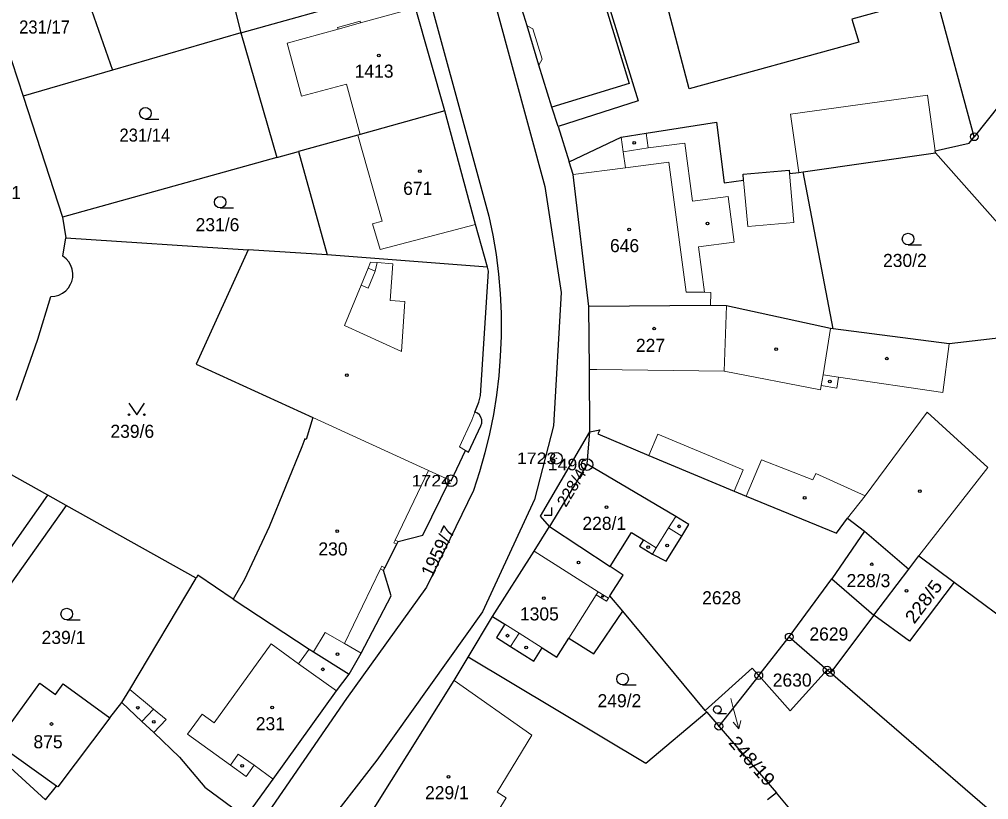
# Model space of a CAD drawing. Extents: x -679733 to -673243, y -1075091 to -1066557.
# Drawn here: x -676181.6 to -676055.6, y -1071788.5 to -1071687 of the extents above; entities that cross this region are included whole.
import ezdxf
from ezdxf.enums import TextEntityAlignment as Align

# ---------------------------------------------------------------- set-up
doc = ezdxf.new("R2010")
doc.units = 0
doc.header["$LTSCALE"] = 0.68
for name, color, linetype, lineweight in [('1', 7, 'Continuous', 25), ('3', 7, 'Continuous', 25), ('4', 7, 'Continuous', 13), ('5', 7, 'Continuous', 25), ('7', 7, 'Continuous', 13), ('8', 7, 'Continuous', 25)]:
    doc.layers.add(name, color=color, linetype=linetype, lineweight=lineweight)
doc.layers.add('2', color=7, linetype='Continuous')

msp = doc.modelspace()

# ---------------------------------------------------------------- linework, layer by layer
at = {"layer": '1'}
for p, q in [((-676057.44, -1071702.25), (-676066.33, -1071669.3)), ((-676152.82, -1071688.75), (-676130.95, -1071682.6)), ((-676181.15, -1071696.97), (-676176.04, -1071712.7)), ((-676111.57, -1071700.93), (-676112.37, -1071698.39)), ((-676111.57, -1071700.93), (-676110.14, -1071705.5)), ((-676062.48, -1071704.34), (-676042.38, -1071727.03)), ((-676075.79, -1071727.22), (-676079.69, -1071706.8)), ((-676107.78, -1071744.81), (-676107.45, -1071740.64)), ((-676175.55, -1071750.2), (-676177.92, -1071748.87)), ((-676071.71, -1071753.55), (-676065.95, -1071758.47)), ((-676092.44, -1071776.86), (-676103.16, -1071763.95)), ((-676070.48, -1071764.46), (-676076.15, -1071771.95)), ((-676081.51, -1071767.29), (-676076.59, -1071771.59)), ((-676169.85, -1071777.83), (-676168.29, -1071775.82))]:
    msp.add_line(p, q, dxfattribs=at)
for points in [[(-676099.38, -1071590.43), (-676125.1, -1071603.36), (-676134.03, -1071611.63), (-676132.28, -1071638.9), (-676113.31, -1071708.7), (-676111.17, -1071722.51), (-676112.16, -1071739.84), (-676114.63, -1071749.43), (-676121.41, -1071764.03), (-676135.15, -1071783.33), (-676142.46, -1071792.76), (-676166.36, -1071822.04), (-676175.39, -1071833.12), (-676182.45, -1071844.4), (-676187.2, -1071855.01), (-676191.45, -1071871.27), (-676192.51, -1071884.43), (-676191.2, -1071899.37), (-676183.88, -1071917.06), (-676171.89, -1071936.65), (-676157.14, -1071950.29), (-676143.77, -1071959.8), (-676108.24, -1071982.64), (-676103.47, -1071979.82)], [(-676152.11, -1071615.93), (-676148.36, -1071616.28), (-676140.37, -1071639.9), (-676120.56, -1071712.56)], [(-676103.2, -1071654.04), (-676086.03, -1071649.36), (-676082.9, -1071651.16), (-676076.65, -1071673.87), (-676071.5, -1071672.48), (-676068, -1071685.48), (-676073.36, -1071686.93), (-676072.45, -1071689.95), (-676094.51, -1071696.03), (-676097.54, -1071684.49)], [(-676112.37, -1071698.39), (-676114.06, -1071692.92), (-676115.61, -1071687.82), (-676116.03, -1071686.43), (-676117.44, -1071681.82), (-676117.87, -1071680.43), (-676119.29, -1071675.81), (-676119.65, -1071674.63), (-676121.9, -1071667.28), (-676122.44, -1071665.53), (-676123.73, -1071661.42)], [(-676042.96, -1071662.97), (-676040.87, -1071672.83), (-676039.2, -1071679.27), (-676057.44, -1071702.25)], [(-676111.15, -1071665.03), (-676104.63, -1071686.35), (-676101.17, -1071697.56), (-676111.57, -1071700.93)], [(-676119.65, -1071674.63), (-676117.65, -1071670.88), (-676116.48, -1071670.53), (-676115.77, -1071670.87), (-676112.25, -1071669.86), (-676111.85, -1071669.11), (-676110.46, -1071668.68), (-676102.32, -1071695.32), (-676112.37, -1071698.39)], [(-676148.81, -1071669.62), (-676151.07, -1071670.28), (-676157.09, -1071671.95), (-676152.82, -1071688.75), (-676148.14, -1071704.96), (-676145.33, -1071704.18)], [(-676174.48, -1071676.86), (-676175.28, -1071677.08), (-676169.53, -1071693.6)], [(-676186.72, -1071680.18), (-676184.08, -1071687.93), (-676181.15, -1071696.97)], [(-676126.28, -1071698.88), (-676130.13, -1071685.49), (-676130.95, -1071682.6)], [(-676152.82, -1071688.75), (-676169.53, -1071693.6), (-676181.15, -1071696.97)], [(-676126.28, -1071698.88), (-676137.33, -1071701.97), (-676137.62, -1071702.05), (-676145.33, -1071704.18), (-676141.6, -1071717.61)], [(-676120.74, -1071719.2), (-676122.3, -1071713.65), (-676126.28, -1071698.88)], [(-676110.14, -1071705.5), (-676103.36, -1071702.29), (-676100.12, -1071701.77), (-676090.96, -1071700.35), (-676089.95, -1071708.22), (-676087.44, -1071707.87), (-676087.51, -1071707.12), (-676081.5, -1071706.6), (-676081.46, -1071707.04), (-676080.26, -1071706.88), (-676079.69, -1071706.8), (-676062.48, -1071704.34)], [(-676062.48, -1071704.34), (-676062.52, -1071704.09), (-676058.1, -1071703.08), (-676057.44, -1071702.25)], [(-676148.14, -1071704.96), (-676176.04, -1071712.7), (-676175.61, -1071715.39), (-676151.9, -1071716.94)], [(-676107.55, -1071724.3), (-676109.62, -1071707.17), (-676110.14, -1071705.5)], [(-676120.56, -1071712.56), (-676120.048, -1071715.059), (-676119.634, -1071717.577), (-676119.319, -1071720.109), (-676119.103, -1071722.651), (-676118.987, -1071725.2), (-676118.971, -1071727.751), (-676118.98, -1071728.231), (-676119.083, -1071730.78), (-676119.285, -1071733.323), (-676119.588, -1071735.857), (-676119.989, -1071738.376), (-676120.489, -1071740.878), (-676121.086, -1071743.359), (-676121.78, -1071745.814), (-676122.57, -1071748.24)], [(-676177.55, -1071723.03), (-676177.018, -1071722.983), (-676176.504, -1071722.837), (-676176.026, -1071722.598), (-676175.601, -1071722.275), (-676175.243, -1071721.878), (-676174.966, -1071721.421), (-676174.822, -1071721.065), (-676174.704, -1071720.544), (-676174.685, -1071720.01), (-676174.765, -1071719.482), (-676174.943, -1071718.978), (-676175.211, -1071718.516), (-676175.561, -1071718.112), (-676175.98, -1071717.78), (-676175.61, -1071715.39)], [(-676151.9, -1071716.94), (-676158.66, -1071731.81), (-676143.45, -1071738.76), (-676144.34, -1071741.61), (-676144.49, -1071741.53), (-676144.89, -1071742.57), (-676149.15, -1071752.96), (-676152.35, -1071759.83), (-676153.84, -1071762.37)], [(-676120.74, -1071719.2), (-676141.6, -1071717.61), (-676151.9, -1071716.94)], [(-676122.39, -1071738.06), (-676121.89, -1071736.77), (-676121.68, -1071735.9), (-676120.6, -1071719.71), (-676120.74, -1071719.2)], [(-676182.03, -1071736.5), (-676179.22, -1071728.58), (-676177.55, -1071723.03)], [(-676075.79, -1071727.22), (-676076.13, -1071727.18), (-676089.68, -1071724.22), (-676091.73, -1071724.19), (-676107.55, -1071724.3)], [(-676107.45, -1071740.64), (-676107.5, -1071732.52), (-676107.55, -1071724.3)], [(-676042.38, -1071727.03), (-676060.72, -1071729.17), (-676075.79, -1071727.22)], [(-676121.62, -1071739.82), (-676121.506, -1071739.486), (-676121.491, -1071739.134), (-676121.5, -1071739.061), (-676121.604, -1071738.724), (-676121.799, -1071738.43), (-676122.068, -1071738.203), (-676122.39, -1071738.06)], [(-676138.75, -1071772.14), (-676137.2, -1071769.4), (-676133.27, -1071761.96), (-676134.28, -1071758.66), (-676134.1, -1071758.3), (-676132.55, -1071755.25), (-676132.37, -1071754.9), (-676129.16, -1071754.05), (-676125.64, -1071746.89), (-676125.49, -1071746.98), (-676123.61, -1071743.03), (-676123.24, -1071743.26), (-676121.62, -1071739.82)], [(-676112.69, -1071752.95), (-676113.86, -1071751.58), (-676107.45, -1071740.64)], [(-676107.45, -1071740.64), (-676106.12, -1071740.38), (-676106.39, -1071740.9), (-676099.76, -1071743.68), (-676088.67, -1071748.33), (-676087.1, -1071748.99), (-676075.34, -1071753.78), (-676073.91, -1071751.86), (-676071.71, -1071753.55)], [(-676195.04, -1071773.17), (-676177.92, -1071748.87), (-676185.65, -1071744.56)], [(-676107.78, -1071744.81), (-676112.69, -1071752.95), (-676104.8, -1071758.15)], [(-676104.8, -1071758.15), (-676102.03, -1071753.7), (-676100.48, -1071754.66), (-676100.99, -1071755.47), (-676099.3, -1071756.52), (-676097.52, -1071757.44), (-676095.49, -1071754.18), (-676094.57, -1071752.69), (-676096.27, -1071751.63), (-676107.78, -1071744.81)], [(-676122.57, -1071748.24), (-676128.67, -1071760.82), (-676139.08, -1071775.3), (-676150.18, -1071791.44), (-676172.35, -1071816.74), (-676187.37, -1071835.51)], [(-676168.29, -1071775.82), (-676167.29, -1071774.14), (-676158.64, -1071759.64), (-676175.55, -1071750.2), (-676193.13, -1071774.91), (-676178.23, -1071788.5), (-676176.79, -1071786.69)], [(-676120.09, -1071764.63), (-676114.68, -1071756.12), (-676112.69, -1071752.95)], [(-676071.71, -1071753.55), (-676075.98, -1071759.72), (-676070.48, -1071764.46), (-676065.95, -1071758.47)], [(-676065.95, -1071758.47), (-676064.66, -1071756.76), (-676060.06, -1071760.17)], [(-676103.16, -1071763.95), (-676104.82, -1071761.95), (-676103.11, -1071759.26), (-676104.8, -1071758.15)], [(-676153.84, -1071762.37), (-676158.41, -1071759.25), (-676158.64, -1071759.64)], [(-676085.46, -1071772.32), (-676081.51, -1071767.29), (-676075.98, -1071759.72)], [(-676060.06, -1071760.17), (-676065.84, -1071767.86), (-676070.48, -1071764.46)], [(-676060.06, -1071760.17), (-676050.81, -1071767.02), (-676048.46, -1071763.85)], [(-676153.84, -1071762.37), (-676143.93, -1071768.88), (-676143.36, -1071769.24), (-676138.75, -1071772.14)], [(-676137.29, -1071792.46), (-676125.09, -1071772.94), (-676123.26, -1071769.92), (-676120.09, -1071764.63)], [(-676120.09, -1071764.63), (-676118.51, -1071765.64), (-676119.59, -1071767.35), (-676117.74, -1071768.53), (-676114.72, -1071770.44), (-676113.63, -1071768.73), (-676111.75, -1071769.93), (-676110.17, -1071767.45), (-676106.92, -1071769.51), (-676103.16, -1071763.95)], [(-676092.24, -1071777.09), (-676100.15, -1071783.77), (-676123.26, -1071769.92)], [(-676152.21, -1071790.73), (-676151.78, -1071790.15), (-676148.63, -1071785.79), (-676140.41, -1071774.31), (-676138.75, -1071772.14)], [(-676085.46, -1071772.32), (-676086.32, -1071771.35), (-676092.44, -1071776.86)], [(-676085.46, -1071772.32), (-676090.66, -1071778.91), (-676083.15, -1071787.56)], [(-676076.59, -1071771.59), (-676081.39, -1071776.9), (-676085.46, -1071772.32)], [(-676044.62, -1071799.18), (-676076.15, -1071771.95), (-676076.59, -1071771.59)], [(-676176.79, -1071786.69), (-676184.64, -1071781.1), (-676178.96, -1071773.29), (-676176.94, -1071774.76), (-676175.94, -1071773.39), (-676169.85, -1071777.83)], [(-676168.29, -1071775.82), (-676165.7, -1071778.29), (-676164.16, -1071779.74), (-676160.82, -1071782.91), (-676157.5, -1071786.82), (-676152.21, -1071790.73)], [(-676092.44, -1071776.86), (-676092.24, -1071777.09), (-676090.66, -1071778.91)], [(-676169.85, -1071777.83), (-676176.63, -1071786.8), (-676176.79, -1071786.69)], [(-676067.25, -1071806.74), (-676075.34, -1071796.95), (-676083.15, -1071787.56), (-676084.33, -1071788.48)]]:
    msp.add_lwpolyline(points, dxfattribs=at)
at = {"layer": '3'}
for p, q in [((-676165.243, -1071699.94), (-676163.493, -1071699.94)), ((-676155.523, -1071711.5), (-676153.773, -1071711.5)), ((-676066.053, -1071716.3), (-676064.303, -1071716.3)), ((-676175.483, -1071765.07), (-676173.733, -1071765.07)), ((-676103.173, -1071773.52), (-676101.423, -1071773.52)), ((-676090.845, -1071777.24), (-676089.673, -1071777.24))]:
    msp.add_line(p, q, dxfattribs=at)
for points in [[(-676167.38, -1071736.889), (-676166.38, -1071738.39), (-676165.38, -1071736.889)], [(-676113.371, -1071751.45), (-676112.37, -1071751.45), (-676112.37, -1071750.45)]]:
    msp.add_lwpolyline(points, dxfattribs=at)
for centre, radius in [((-676165.2429, -1071699.1898), 0.75), ((-676155.5229, -1071710.7498), 0.75), ((-676066.0529, -1071715.5498), 0.75), ((-676167.38, -1071738.3895), 0.1), ((-676165.38, -1071738.3895), 0.1), ((-676175.4829, -1071764.3198), 0.75), ((-676103.1729, -1071772.7698), 0.75), ((-676090.8452, -1071776.7374), 0.5025)]:
    msp.add_circle(centre, radius, dxfattribs=at)
at = {"layer": '4'}
for p, q in [((-676137.25, -1071687.44), (-676130.13, -1071685.49)), ((-676140.24, -1071688.04), (-676137.31, -1071687.23)), ((-676140.18, -1071688.25), (-676137.25, -1071687.44)), ((-676137.31, -1071687.23), (-676137.25, -1071687.44)), ((-676115.61, -1071687.82), (-676114.86, -1071688.22)), ((-676146.79, -1071690.08), (-676140.18, -1071688.25)), ((-676140.18, -1071688.25), (-676140.24, -1071688.04)), ((-676114.86, -1071688.22), (-676113.65, -1071692.17)), ((-676144.95, -1071696.98), (-676146.79, -1071690.08)), ((-676113.65, -1071692.17), (-676114.06, -1071692.92)), ((-676139.08, -1071695.41), (-676144.95, -1071696.98)), ((-676137.33, -1071701.97), (-676139.08, -1071695.41)), ((-676081.34, -1071699.31), (-676063.53, -1071696.83)), ((-676063.53, -1071696.83), (-676062.52, -1071704.09)), ((-676081.34, -1071699.31), (-676080.26, -1071706.88)), ((-676099.87, -1071703.69), (-676100.12, -1071701.77)), ((-676134.47, -1071713.22), (-676137.62, -1071702.05)), ((-676103.09, -1071704.19), (-676103.36, -1071702.29)), ((-676099.87, -1071703.69), (-676095.08, -1071703.07)), ((-676095.08, -1071703.07), (-676094.09, -1071710.63)), ((-676102.78, -1071706.29), (-676097.15, -1071705.56)), ((-676097.15, -1071705.56), (-676094.92, -1071722.44)), ((-676109.62, -1071707.17), (-676102.78, -1071706.29)), ((-676086.9, -1071713.93), (-676087.44, -1071707.87)), ((-676081.46, -1071707.04), (-676080.89, -1071713.39)), ((-676094.09, -1071710.63), (-676089.44, -1071710.02)), ((-676089.44, -1071710.02), (-676088.66, -1071715.97)), ((-676135.72, -1071713.58), (-676134.47, -1071713.22)), ((-676134.71, -1071716.89), (-676135.72, -1071713.58)), ((-676122.3, -1071713.65), (-676134.71, -1071716.89)), ((-676080.89, -1071713.39), (-676086.9, -1071713.93)), ((-676088.66, -1071715.97), (-676093.29, -1071716.58)), ((-676093.29, -1071716.58), (-676092.51, -1071722.47)), ((-676136.29, -1071719.33), (-676137.2, -1071721.55)), ((-676135.96, -1071718.54), (-676136.29, -1071719.33)), ((-676135.12, -1071718.61), (-676135.96, -1071718.54)), ((-676133.07, -1071718.76), (-676135.12, -1071718.61)), ((-676133.07, -1071718.76), (-676133.39, -1071723.55)), ((-676135.36, -1071719.71), (-676136.28, -1071721.93)), ((-676137.2, -1071721.55), (-676139.36, -1071726.77)), ((-676136.28, -1071721.93), (-676137.2, -1071721.55)), ((-676094.92, -1071722.44), (-676092.51, -1071722.47)), ((-676092.51, -1071722.47), (-676091.71, -1071722.48)), ((-676091.71, -1071722.48), (-676091.73, -1071724.19)), ((-676133.39, -1071723.55), (-676131.5, -1071723.68)), ((-676131.93, -1071730.16), (-676131.5, -1071723.68)), ((-676089.68, -1071724.22), (-676089.95, -1071732.72)), ((-676131.93, -1071730.16), (-676139.36, -1071726.77)), ((-676077.1, -1071733.19), (-676076.13, -1071727.18)), ((-676061.52, -1071735.51), (-676060.72, -1071729.17)), ((-676107.5, -1071732.52), (-676106.51, -1071732.53)), ((-676106.51, -1071732.53), (-676089.95, -1071732.72)), ((-676089.95, -1071732.72), (-676077.42, -1071735.17)), ((-676077.33, -1071734.59), (-676077.1, -1071733.19)), ((-676077.1, -1071733.19), (-676075.08, -1071733.49)), ((-676077.42, -1071735.17), (-676077.33, -1071734.59)), ((-676077.33, -1071734.59), (-676075.31, -1071734.92)), ((-676075.31, -1071734.92), (-676075.08, -1071733.49)), ((-676075.08, -1071733.49), (-676061.52, -1071735.51)), ((-676122.8, -1071739.1), (-676122.39, -1071738.06)), ((-676071.64, -1071748.94), (-676063.57, -1071738.05)), ((-676063.57, -1071738.05), (-676055.69, -1071745.25)), ((-676143.45, -1071738.76), (-676128.42, -1071745.64)), ((-676124.39, -1071742.56), (-676122.8, -1071739.1)), ((-676099.76, -1071743.68), (-676098.6, -1071740.91)), ((-676098.6, -1071740.91), (-676087.51, -1071745.56)), ((-676123.61, -1071743.03), (-676124.39, -1071742.56)), ((-676085.12, -1071744.28), (-676087.1, -1071748.99)), ((-676085.12, -1071744.28), (-676078.42, -1071746.88)), ((-676128.42, -1071745.64), (-676132.77, -1071754.69)), ((-676128.42, -1071745.64), (-676125.64, -1071746.89)), ((-676087.51, -1071745.56), (-676088.67, -1071748.33)), ((-676055.69, -1071745.25), (-676064.66, -1071756.76)), ((-676078.42, -1071746.88), (-676078.05, -1071746.04)), ((-676078.05, -1071746.04), (-676071.64, -1071748.94)), ((-676073.91, -1071751.86), (-676071.64, -1071748.94)), ((-676097.19, -1071753.12), (-676096.27, -1071751.63)), ((-676098.8, -1071755.7), (-676097.19, -1071753.12)), ((-676097.19, -1071753.12), (-676095.49, -1071754.18)), ((-676132.95, -1071755.05), (-676132.77, -1071754.69)), ((-676132.77, -1071754.69), (-676132.37, -1071754.9)), ((-676100.48, -1071754.66), (-676098.8, -1071755.7)), ((-676132.55, -1071755.25), (-676132.95, -1071755.05)), ((-676099.3, -1071756.52), (-676098.8, -1071755.7)), ((-676114.68, -1071756.12), (-676106.34, -1071761.41)), ((-676139.35, -1071768.16), (-676134.68, -1071758.45)), ((-676134.68, -1071758.45), (-676134.5, -1071758.09)), ((-676134.28, -1071758.66), (-676134.68, -1071758.45)), ((-676134.5, -1071758.09), (-676134.1, -1071758.3)), ((-676106.6, -1071761.82), (-676110.17, -1071767.45)), ((-676106.34, -1071761.41), (-676106.6, -1071761.82)), ((-676105.28, -1071762.66), (-676106.6, -1071761.82)), ((-676105.02, -1071762.25), (-676106.34, -1071761.41)), ((-676105.02, -1071762.25), (-676105.28, -1071762.66)), ((-676104.82, -1071761.95), (-676105.02, -1071762.25)), ((-676118.51, -1071765.64), (-676116.65, -1071766.81)), ((-676143.36, -1071769.24), (-676141.85, -1071766.72)), ((-676141.85, -1071766.72), (-676139.35, -1071768.16)), ((-676116.65, -1071766.81), (-676117.74, -1071768.53)), ((-676116.65, -1071766.81), (-676113.63, -1071768.73)), ((-676156.29, -1071778.47), (-676148.89, -1071768.2)), ((-676148.89, -1071768.2), (-676145.32, -1071770.78)), ((-676139.35, -1071768.16), (-676137.2, -1071769.4)), ((-676145.32, -1071770.78), (-676143.93, -1071768.88)), ((-676145.32, -1071770.78), (-676140.41, -1071774.31)), ((-676125.09, -1071772.94), (-676114.97, -1071780.06)), ((-676167.29, -1071774.14), (-676164.19, -1071776.7)), ((-676164.19, -1071776.7), (-676165.7, -1071778.29)), ((-676164.19, -1071776.7), (-676162.55, -1071778.05)), ((-676159.77, -1071779.95), (-676157.88, -1071777.33)), ((-676157.88, -1071777.33), (-676156.29, -1071778.47)), ((-676162.55, -1071778.05), (-676164.16, -1071779.74)), ((-676154.19, -1071783.97), (-676159.77, -1071779.95)), ((-676114.97, -1071780.06), (-676119.48, -1071787.5)), ((-676154.19, -1071783.97), (-676153.16, -1071782.53)), ((-676153.16, -1071782.53), (-676151.12, -1071783.99)), ((-676152.16, -1071785.44), (-676154.19, -1071783.97)), ((-676151.12, -1071783.99), (-676152.16, -1071785.44)), ((-676148.63, -1071785.79), (-676151.12, -1071783.99)), ((-676119.48, -1071787.5), (-676118.32, -1071788.2)), ((-676118.32, -1071788.2), (-676121.02, -1071792.64))]:
    msp.add_line(p, q, dxfattribs=at)
for points in [[(-676102.78, -1071706.29), (-676103.09, -1071704.19), (-676099.87, -1071703.69)], [(-676135.12, -1071718.61), (-676135.36, -1071719.71), (-676136.29, -1071719.33)]]:
    msp.add_lwpolyline(points, dxfattribs=at)
at = {"layer": '5'}
for centre, radius in [((-676134.8968, -1071691.6792), 0.175), ((-676101.6568, -1071703.0292), 0.175), ((-676129.5568, -1071706.7192), 0.175), ((-676102.3268, -1071714.3092), 0.175), ((-676092.1468, -1071713.5192), 0.175), ((-676099.0768, -1071727.1992), 0.175), ((-676083.2168, -1071729.8592), 0.175), ((-676068.7968, -1071731.0992), 0.175), ((-676139.0568, -1071733.2392), 0.175), ((-676076.2268, -1071734.0592), 0.175), ((-676064.5268, -1071748.3492), 0.175), ((-676079.4968, -1071749.1892), 0.175), ((-676105.2768, -1071750.4192), 0.175), ((-676140.2868, -1071753.5292), 0.175), ((-676095.8368, -1071752.9092), 0.175), ((-676099.8468, -1071755.6292), 0.175), ((-676097.3768, -1071755.3892), 0.175), ((-676108.8968, -1071757.5992), 0.175), ((-676070.7768, -1071757.8492), 0.175), ((-676113.4368, -1071762.2592), 0.175), ((-676105.7846, -1071762.0194), 0.1172), ((-676066.2568, -1071761.3092), 0.175), ((-676118.1368, -1071767.1292), 0.175), ((-676115.7268, -1071768.6592), 0.175), ((-676140.2468, -1071769.5492), 0.175), ((-676142.1768, -1071771.5092), 0.175), ((-676166.2168, -1071776.4992), 0.175), ((-676148.7668, -1071776.4792), 0.175), ((-676177.4668, -1071778.6192), 0.175), ((-676164.1668, -1071778.3292), 0.175), ((-676152.6468, -1071784.0592), 0.175), ((-676125.8168, -1071785.4992), 0.175)]:
    msp.add_circle(centre, radius, dxfattribs=at)
at = {"layer": '7'}
msp.add_line((-676088.043, -1071779.239), (-676087.819, -1071778.142), dxfattribs=at)
msp.add_lwpolyline([(-676089.09, -1071775.3), (-676088.82, -1071776.34), (-676088.043, -1071779.239), (-676088.786, -1071778.401)], dxfattribs=at)
at = {"layer": '8'}
for centre, radius in [((-676057.44, -1071702.2499), 0.5), ((-676057.44, -1071702.2499), 0.0303), ((-676111.79, -1071744.0598), 0.75), ((-676111.79, -1071744.0598), 0.03), ((-676107.78, -1071744.8798), 0.75), ((-676107.78, -1071744.8798), 0.03), ((-676125.49, -1071746.9798), 0.75), ((-676125.49, -1071746.9798), 0.03), ((-676081.51, -1071767.2899), 0.5), ((-676081.51, -1071767.2899), 0.0303), ((-676076.59, -1071771.5899), 0.5), ((-676085.46, -1071772.3199), 0.5), ((-676085.46, -1071772.3199), 0.0303), ((-676076.15, -1071771.9499), 0.5), ((-676076.59, -1071771.5899), 0.0303), ((-676076.15, -1071771.9499), 0.0303), ((-676090.66, -1071778.9099), 0.5), ((-676090.66, -1071778.9099), 0.0303)]:
    msp.add_circle(centre, radius, dxfattribs=at)

# ---------------------------------------------------------------- texts
at = {"layer": '2', "width": 0.95}
for s, p in [('231/17', (-676178.369, -1071688.82)), ('231/14', (-676165.319, -1071702.88))]:
    msp.add_text(s, height=1.7, dxfattribs=at).set_placement(p, align=Align.CENTER)
at = {"layer": '2'}
for s, p in [('1413', (-676135.5, -1071694.56)), ('671', (-676129.819, -1071709.8)), ('234/1', (-676184.27, -1071710.35)), ('231/6', (-676155.87, -1071714.529)), ('646', (-676102.919, -1071717.249)), ('230/2', (-676066.46, -1071719.18)), ('227', (-676099.549, -1071730.22)), ('239/6', (-676166.95, -1071741.4)), ('228/1', (-676105.56, -1071753.37)), ('230', (-676140.849, -1071756.7)), ('228/3', (-676071.2, -1071760.82)), ('2628', (-676090.3, -1071763.05)), ('1305', (-676114, -1071765.15)), ('2629', (-676076.35, -1071767.759)), ('239/1', (-676175.9, -1071768.21)), ('2630', (-676081.12, -1071773.759)), ('249/2', (-676103.59, -1071776.44)), ('231', (-676148.989, -1071779.43)), ('875', (-676177.909, -1071781.779)), ('229/1', (-676126.03, -1071788.4))]:
    msp.add_text(s, height=1.7, dxfattribs=at).set_placement(p, align=Align.CENTER)
for s, height, rotation, width, p in [('228/4', 1.5, 59, 1.05, (-676109.1918, -1071748.2578)), ('228/5', 1.7, 53, 1.1, (-676063.3539, -1071763.2))]:
    msp.add_text(s, height=height, rotation=rotation, dxfattribs=dict(at, width=width)).set_placement(p, align=Align.CENTER)
msp.add_text('1959/7', height=1.7, rotation=64, dxfattribs=at).set_placement((-676126.4246, -1071756.5231), align=Align.CENTER)
at = {"layer": '2', "width": 1.1}
msp.add_text('248/19', height=1.7, rotation=311, dxfattribs=at).set_placement((-676089.488, -1071781.098))
at = {"layer": '8', "width": 1.15}
for s, p in [('1723', (-676111.789, -1071744.81)), ('1496', (-676107.779, -1071745.629)), ('1724', (-676125.489, -1071747.73))]:
    msp.add_text(s, height=1.5, dxfattribs=at).set_placement(p, align=Align.RIGHT)

doc.saveas('drawing.dxf')
